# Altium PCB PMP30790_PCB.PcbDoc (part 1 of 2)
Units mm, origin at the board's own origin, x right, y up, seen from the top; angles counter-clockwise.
Board outline 83.5 x 82.5 mm, 4 copper layers (Top Layer, GND, Signal Layer, Bottom Layer), stack 2.155 mm thick; 81 components, 34 nets, 189 pads, 254 vias.
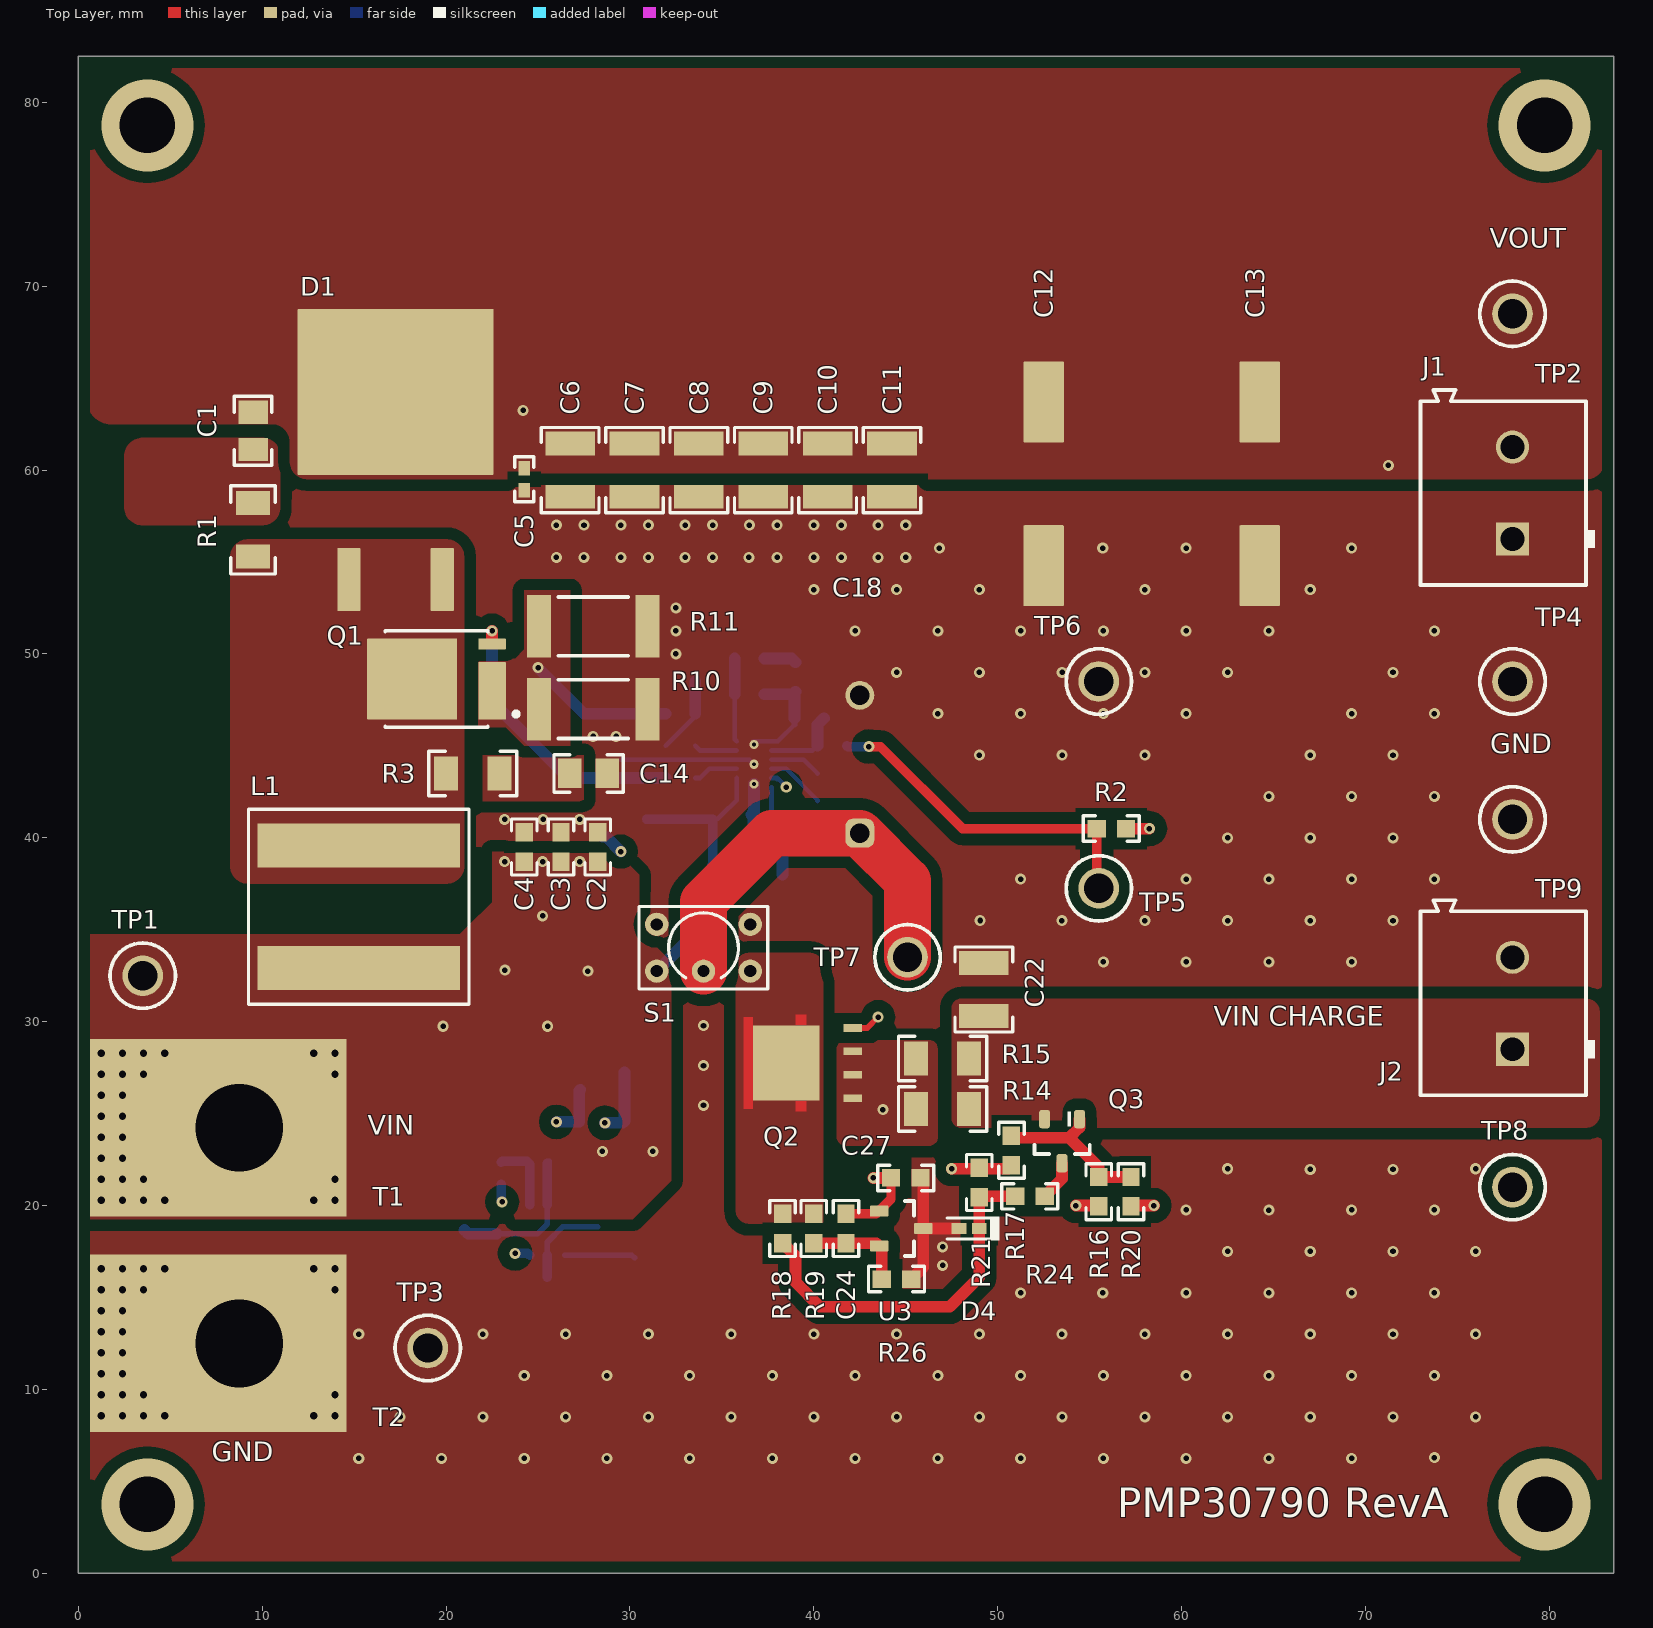
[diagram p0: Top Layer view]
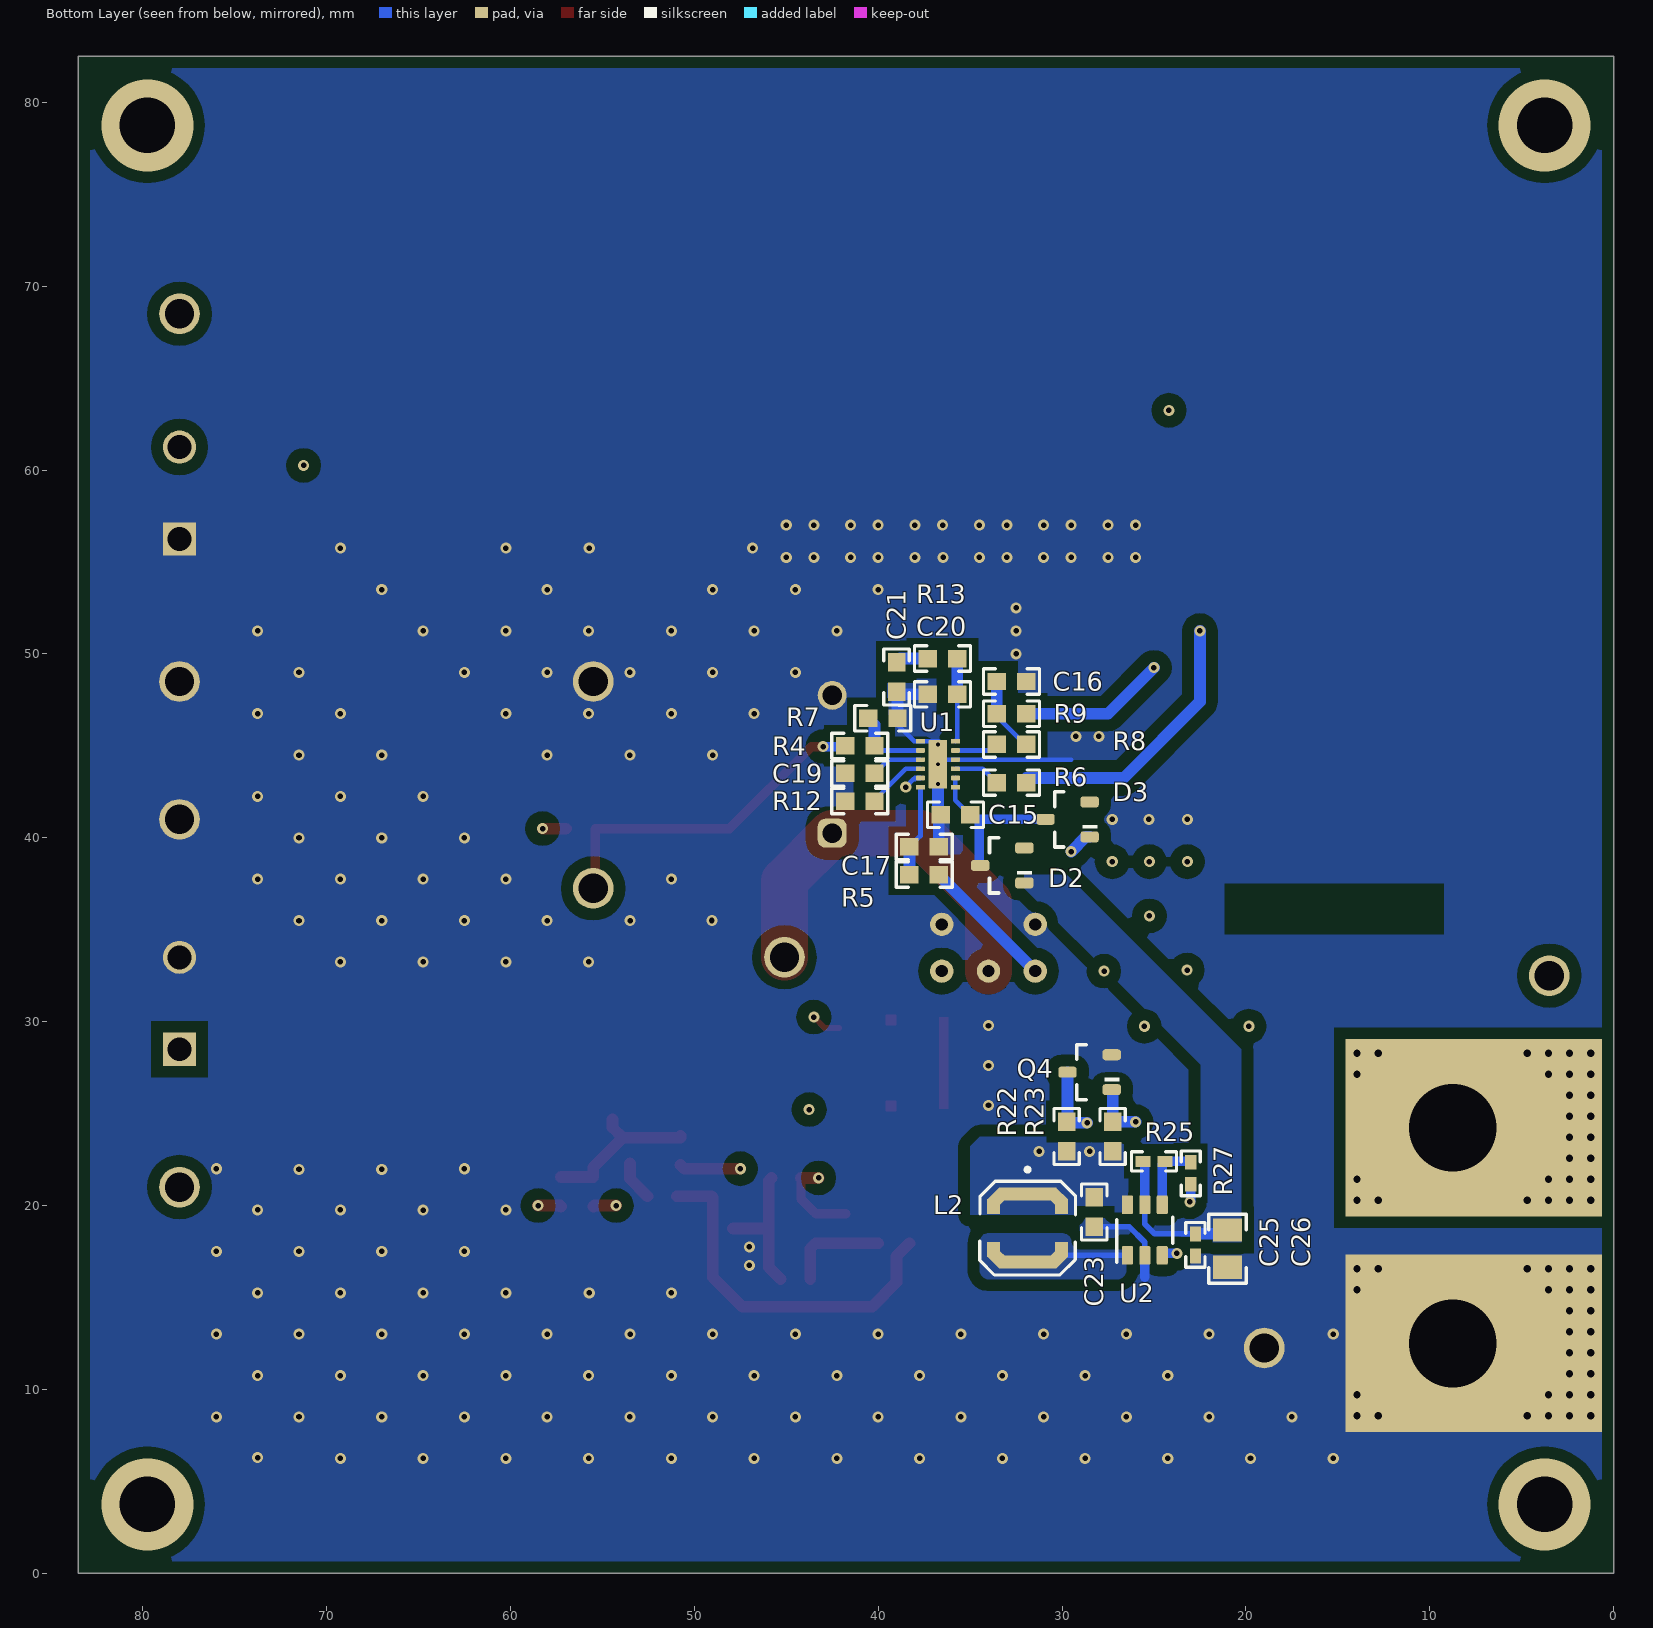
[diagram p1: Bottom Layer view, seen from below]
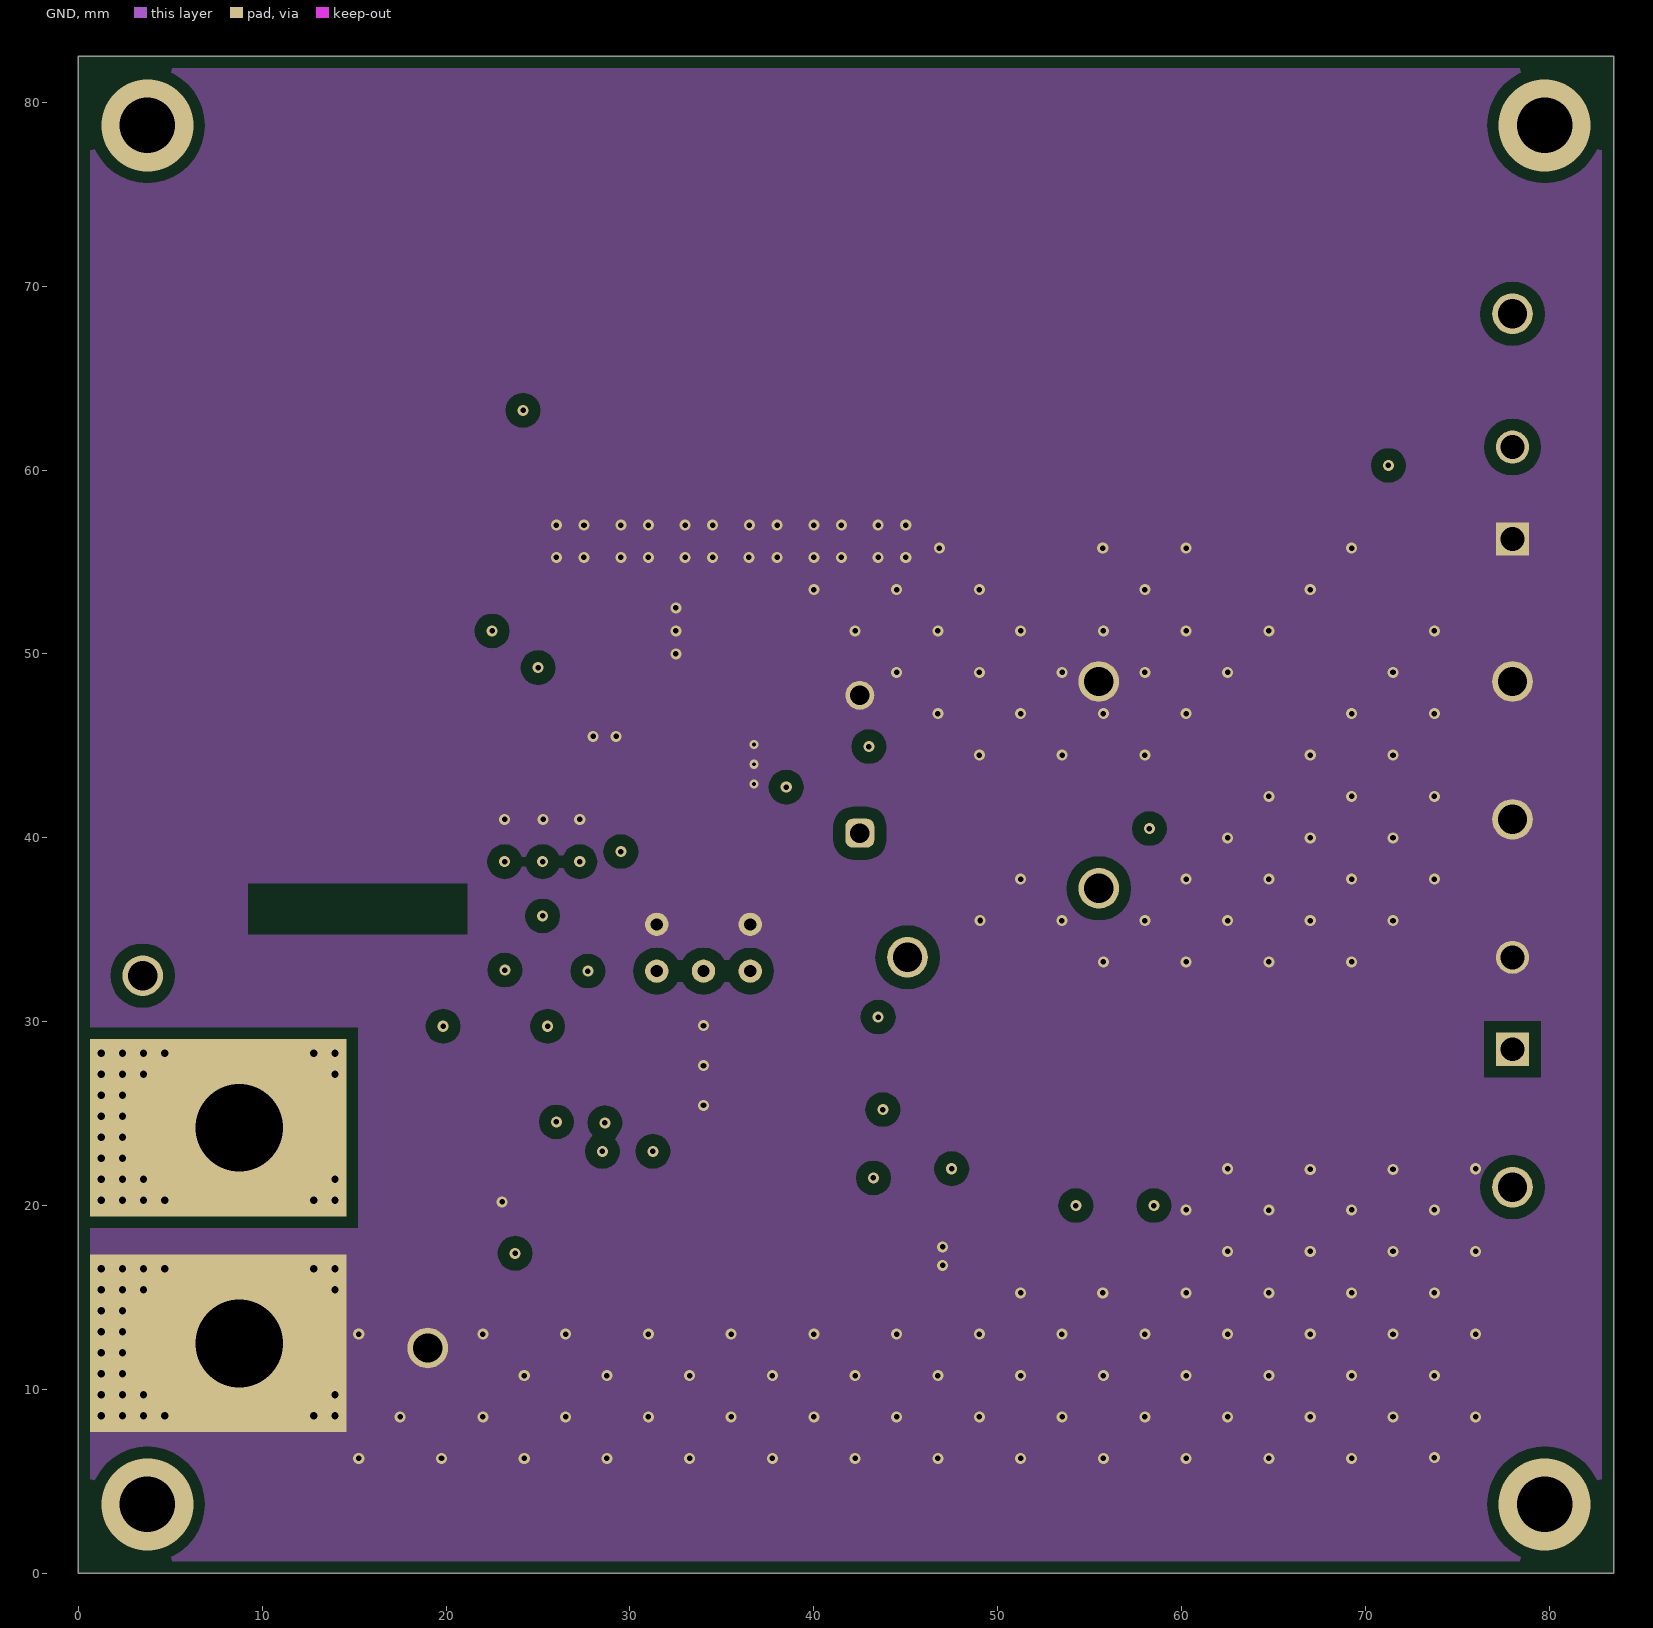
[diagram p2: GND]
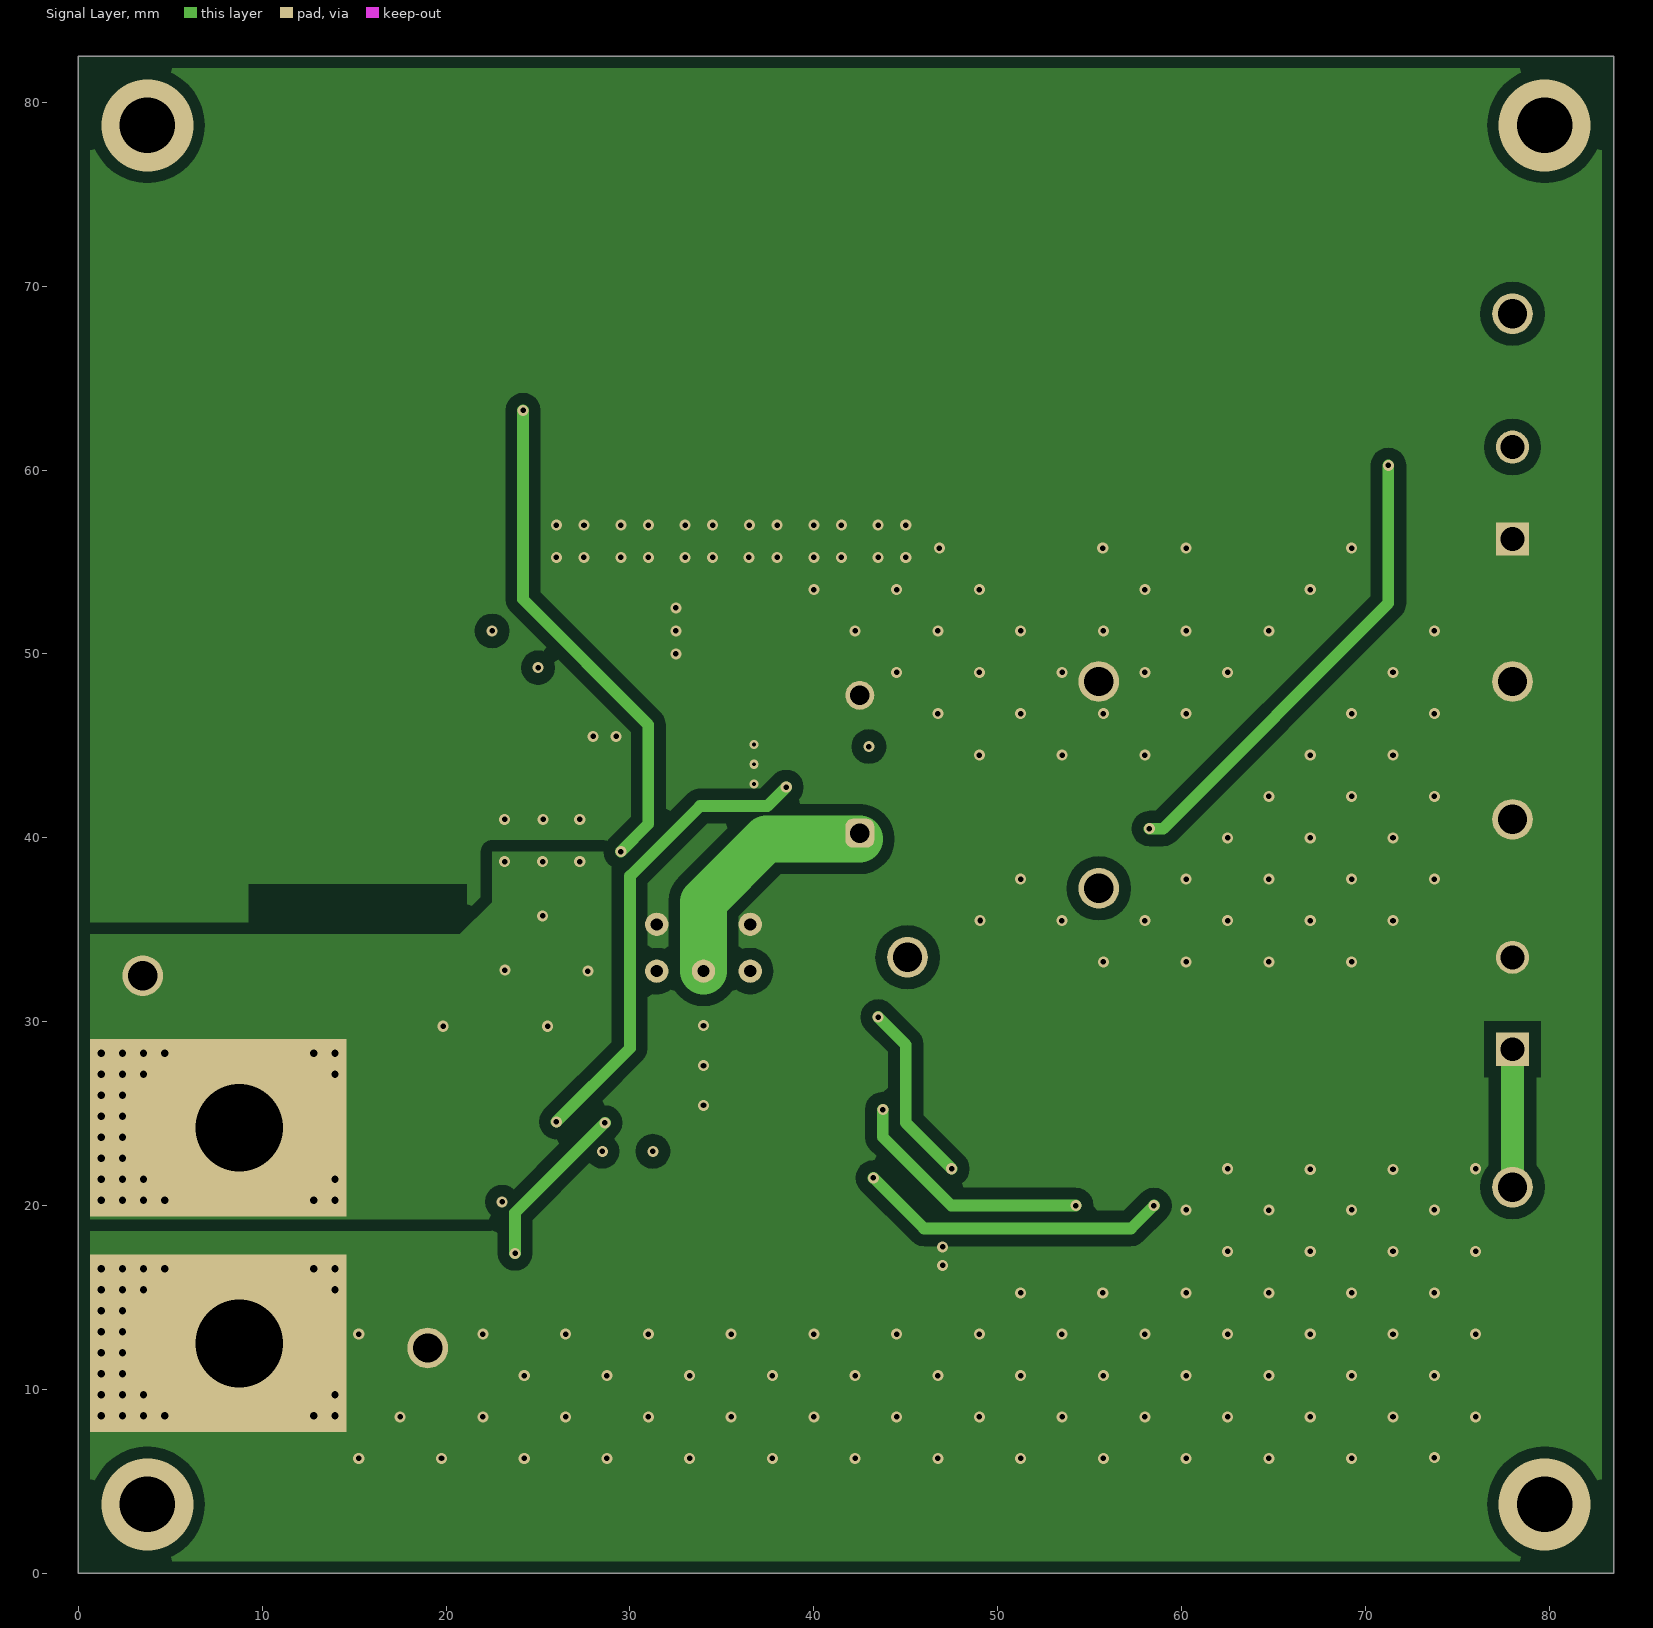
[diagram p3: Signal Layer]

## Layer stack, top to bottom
Top Solder: solder mask 0.0102, Solder Resist, Dk 3.5
Top Layer: signal copper 0.0356
Dielectric 2: dielectric 0.254, Dk 4.2
GND: signal copper 0.036
Dielectric1: core 1.5037, FR-4, Dk 4.8
Signal Layer: signal copper 0.036
Dielectric 3: dielectric 0.254, Dk 4.2
Bottom Layer: signal copper 0.0356
Bottom Solder: solder mask 0.0102, Solder Resist, Dk 3.5

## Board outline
0,0 83.5,0 83.5,82.5 0,82.5

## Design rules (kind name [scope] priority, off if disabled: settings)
AcuteAngle [All] p1: minimum=4.50000000000000E+0001 checktracksonly=FALSE
AssemblyTestPointUsage [All] p1: valid=2
BoardOutlineClearance BoardOutlineClearance_MountingHoles [OnCopper and InComponentClass('Mounting Holes')] p1: gap=1 ignorepadtopadclearanceinfootprint=FALSE
BoardOutlineClearance BoardOutlineClearance_Poly [OnCopper and IsPoly] p2: gap=0.635 ignorepadtopadclearanceinfootprint=FALSE
BoardOutlineClearance [OnCopper and Not InComponentClass('Logo') and not InComponentClass('FiducialMark') and not InRegion(1000,500,4000,800) and not InPoly] p3: gap=1.905 ignorepadtopadclearanceinfootprint=FALSE
Clearance Clearance_Keepouts [((IsTrack Or IsArc) And Not InPoly) And IsFree and IsKeepOut vs ((IsTrack Or IsArc) And Not InPoly) And IsFree and IsKeepOut] p1: gap=0 ignorepadtopadclearanceinfootprint=FALSE
Clearance Clearance_Poly [InPolygon] p2: gap=0.635 ignorepadtopadclearanceinfootprint=TRUE
Clearance Clearance_FiducialMark [IsKeepOut and InComponentClass('FiducialMark') vs IsPad and InComponentClass('FiducialMark')] p3: gap=0 ignorepadtopadclearanceinfootprint=FALSE
Clearance [All] p4: gap=0.2 ignorepadtopadclearanceinfootprint=TRUE
ComponentClearance ComponentClearance_MountingHoles_FiducialMarks [InComponentClass('Mounting Holes') vs InComponentClass('FiducialMark')] p1: gap=1.27 collisioncheckmode=3 verticalgap=0.254 showdistances=FALSE
ComponentClearance ComponentClearance_Shunt [InComponentClass('Header') vs InComponentClass('Shunt')] p2: gap=0 collisioncheckmode=3 verticalgap=0 showdistances=FALSE
ComponentClearance ComponentClearance_Logo [InComponentClass('Logo')] p3: gap=1.27 collisioncheckmode=3 verticalgap=0.254 showdistances=FALSE
ComponentClearance ComponentClearance_ScrewToNut [(HasFootprint('NY PMS 440 0025 PH')) vs (HasFootprint('Keystone_1902C'))] p4: gap=0.127 collisioncheckmode=3 verticalgap=0.254 showdistances=FALSE
ComponentClearance ComponentClearance_MountingHoles [InComponentClass('Mounting Holes')] p5: gap=6.35 collisioncheckmode=3 verticalgap=2540 showdistances=FALSE
ComponentClearance ComponentClearance_SmallPassives [HasFootprint('0201*') or HasFootprint('0402*') or HasFootprint('0508') or HasFootprint('0603*') or HasFootprint('0612') or HasFootprint('0805*') or HasFootprint('0815*') or HasFootprint('0830*') or HasFootprint('1206*') or HasFootprint('1210*') or HasFootprint('1808*') or HasFootprint('1812*') or HasFootprint('1825*') or HasFootprint('2010*') or HasFootprint('2220*') or HasFootprint('2225*') or HasFootprint('2512*') or HasFootprint('2728*') or HasFootprint('3518*') vs HasFootprint('0201*') or HasFootprint('0402*') or HasFootprint('0508') or HasFootprint('0603*') or HasFootprint('0612') or HasFootprint('0805*') or HasFootprint('0815*') or HasFootprint('0830*') or HasFootprint('1206*') or HasFootprint('1210*') or HasFootprint('1808*') or HasFootprint('1812*') or HasFootprint('1825*') or HasFootprint('2010*') or HasFootprint('2220*') or HasFootprint('2225*') or HasFootprint('2512*') or HasFootprint('2728*') or HasFootprint('3518*')] p6: gap=0.38 collisioncheckmode=3 verticalgap=0.254 showdistances=FALSE
ComponentClearance ComponentClearance_THtoSMT [IsThruComponent vs IsSMTComponent] p7: gap=1.016 collisioncheckmode=3 verticalgap=0.762 showdistances=FALSE
ComponentClearance ComponentClearance_THtoTH [IsThruComponent vs IsThruComponent] p8: gap=0.762 collisioncheckmode=3 verticalgap=0.762 showdistances=FALSE
ComponentClearance [All] p9: gap=0.762 collisioncheckmode=3 verticalgap=0.254 showdistances=FALSE
DiffPairsRouting [All] p1: maxlimit=2.54 minlimit=0.254 mostfreqgap=0.254 toplayer_minwidth=0.381 toplayer_maxwidth=0.381 toplayer_prefwidth=0.381 midlayer1_minwidth=0.381 midlayer1_maxwidth=0.381 midlayer1_prefwidth=0.381 midlayer2_minwidth=0.381 midlayer2_maxwidth=0.381 midlayer2_prefwidth=0.381 bottomlayer_minwidth=0.381 bottomlayer_maxwidth=0.381 bottomlayer_prefwidth=0.381 maxuncoupledlength=25.4
FabricationTestPointUsage TestPointUsage [All] p1: valid=2 allowmultiple=FALSE
FabricationTestpoint Testpoint [All] p1: side=3 testpointundercomponent=TRUE minsize=1.016 maxsize=2.54 preferedsize=1.524 minholesize=0 maxholesize=1.016 preferedholesize=0.813 testpointgrid=0.025 allowsidetop=TRUE allowsidebottom=TRUE usegrid=TRUE gridtolerance=0
FanoutControl Fanout_LCC [IsLCC] p1: bgadir=Out bgaviamode=Centered fanoutstyle=Auto fanoutdirection=Alternating viagrid=0.025 // Fanout_LCC (Default Rule)
FanoutControl Fanout_BGA [IsBGA] p2: bgadir=Out bgaviamode=Centered fanoutstyle=Auto fanoutdirection=Alternating viagrid=0.025 // Fanout_BGA (Default Rule)
FanoutControl Fanout_Default [All] p4: bgadir=Out bgaviamode=Centered fanoutstyle=Auto fanoutdirection=Alternating viagrid=0.025 // Fanout_Default (Default Rule)
FanoutControl Fanout_Small [(CompPinCount < 5)] p5: bgadir=Out bgaviamode=Centered fanoutstyle=Auto fanoutdirection=OutThenIn viagrid=0.025 // Fanout_Small (Default Rule)
HoleSize [All] p1: absolutevalues=TRUE maxlimit=6.375 minlimit=0.2 maxpercent=80.000 minpercent=20.000
MinimumAnnularRing MinimumAnnularRing_ThermalPadVias [IsVia and InAnyComponent] p1: minimumring=0.15
MinimumAnnularRing [All] p2: minimumring=0.2
MinimumSolderMaskSliver MinimumSolderMaskSliver_Logo [InComponentClass('Logo') vs InComponentClass('Logo')] p1: minsoldermaskwidth=0.018
MinimumSolderMaskSliver [All] p2: minsoldermaskwidth=0.1
PlaneConnect [All] p1: planeconnectstyle=Direct reliefexpansion=0.254 reliefentries=4 reliefconductorwidth=0.254 reliefairgap=0.254
PolygonConnect PolygonConnect_1 [All vs IsNamedPolygon('TOP_LAYER_NETD1_1_P000')] p1: connectstyle=Direct reliefconductorwidth=0.254 reliefentries=4 polygonreliefangle="90 Angle" airgapwidth=0.254
PolygonConnect [All] p2: connectstyle=Direct reliefconductorwidth=0.254 reliefentries=4 polygonreliefangle="90 Angle" airgapwidth=0.254
RoutingVias ThermalPadVias [IsVia and InAnyComponent] p1: holewidth=0.2 width=0.5 viastyle="Through Hole" minholewidth=0.2 minwidth=0.5 maxholewidth=0.33 maxwidth=0.6
RoutingVias [All] p2: holewidth=0.406 width=0.864 viastyle="Through Hole" minholewidth=0.2 minwidth=0.66 maxholewidth=1.016 maxwidth=1.651
SilkToBoardRegionClearance [Not ((IsComment or IsDesignator) And (Hide <> 'False')) and not InRegion(1000,500,4000,800)] p1:
SilkToSilkClearance SilkToSilkClearance_Pb-FreeLogo [(HasFootprint('Pb-Free_Overlay_Medium') OR HasFootprint('Pb-Free_Overlay_Small')) vs (HasFootprint('Pb-Free_Overlay_Medium') OR HasFootprint('Pb-Free_Overlay_Small'))] p1: silktosilkclearance=0
SilkToSilkClearance [All] p2: silktosilkclearance=0.1
SilkToSolderMaskClearance SilkToComponentPadClearance [(IsPad or IsFill or IsRegion) and InAnycomponent] p1: minsilkscreentomaskgap=0.127 clearancetoexposedcopper=TRUE
SilkToSolderMaskClearance "Silk to Solder Mask Opening" [All] p2: minsilkscreentomaskgap=0.1 clearancetoexposedcopper=FALSE
SolderMaskExpansion [All] p1: expansion=0.05
UnRoutedNet [All] p1: checkbadconnections=TRUE
Width [All] p1: maxlimit=2.54 minlimit=0.152 preferedwidth=0.254 checkconnectedcopper=TRUE
14 further rules are at their usual default settings.

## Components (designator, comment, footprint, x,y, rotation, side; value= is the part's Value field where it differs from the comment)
C1 "GRM21AR72E102KW01D" 0805_HV 9.5,62.134 r270 top value=1000pF
C2 "GRM188Z71A106MA73D" 0603 28.25,39.5 r90 top value=10uF
C3 "GRM188Z71A106MA73D" 0603 26.25,39.5 r90 top value=10uF
C4 "GRM188Z71A106MA73D" 0603 24.25,39.5 r90 top value=10uF
C5 "GRM155R71C104JA88D" 0402 24.25,59.5 r270 top value=0.1uF
C6 "GRM32ER71E226KE15L" 1210_270 26.75,60 r270 top value=22uF
C7 "GRM32ER71E226KE15L" 1210_270 30.25,60 r270 top value=22uF
C8 "GRM32ER71E226KE15L" 1210_270 33.75,60 r270 top value=22uF
C9 "GRM32ER71E226KE15L" 1210_270 37.25,60 r270 top value=22uF
C10 "GRM32ER71E226KE15L" 1210_270 40.75,60 r270 top value=22uF
C11 "GRM32ER71E226KE15L" 1210_270 44.25,60 r270 top value=22uF
C12 "HHXB160ARA471MJA0G" FP-HHXB160ARA471MJA0G_RADIAL-MFG 52.5,59.25 r90 top
C13 "HHXB160ARA471MJA0G" FP-HHXB160ARA471MJA0G_RADIAL-MFG 64.25,59.25 r90 top
C14 "GRM21AR72E102KW01D" 0805_HV 27.75,43.5 r0 top value=1000pF
C15 "GRM188Z71C225KE43" 0603 35.8,41.25 r0 bottom value=2.2uF
C16 "GRM188R71C102KA01D" 0603 32.75,48.5 r180 bottom value=1000pF
C17 "GRM188R71C104KA01D" 0603 37.5,39.5 r180 bottom value=0.1uF
C18 "JUMT1226MHD" JUM_1600x3150 42.5,44 r90 top value=22000000uF
C19 "GRM188R71C104KA01D" 0603 41,43.5 r0 bottom value=0.1uF
C20 "GRM188R71H223KA01D" 0603 36.5,47.8 r0 bottom value=0.022uF
C21 "GRM188R71A684KA61D" 0603 39,48.75 r270 bottom value=0.68uF
C22 "GRM32ER71H475KA88L" 1210_270 49.25,31.75 r90 top value=4.7uF
C23 "GRM188Z71A106MA73D" 0603 28.25,19.65 r270 bottom value=10uF
C24 "GRM188R72A102KA01D" 0603 41.75,18.75 r270 top value=1000pF
C25 "GRM155R71A104KA01D" 0402 22.75,17.856 r270 bottom value=0.1uF
C26 "GRM21BZ71E106KE15L" 0805_HV 21,17.65 r270 bottom value=10uF
C27 "GRM188R72A102KA01D" 0603 45,21.5 r0 top value=1000pF
D1 "MBRB1535CTPBF" DDPAK 17.25,60.3 r90 top value=35V
D2 "BAS16LT1G" SOT-23 33.25,38.5 r0 bottom value=100V
D3 "BAS16LT1G" SOT-23 29.7,41 r0 bottom value=100V
D4 "DNP" SOD-523 48.45,18.75 r180 top value=2.7V
J1 "691 101 710 002" Wurth_691101710002 78,58.75 r90 top
J2 "691 101 710 002" Wurth_691101710002 78,31 r90 top
L1 "XAL1060-122MEB" XAL1060 15.25,36.25 r90 top value=1.2uH
L2 "LPS4018-103MRB" LPS4018 31.876,18.774 r270 bottom value=10uH
Q1 "IAUC120N04S6N010ATMA1" FP-IAUC120N04S6N009ATMA1_TDSON8-MFG 19.48,48.635 r90 top
Q2 "SQJ415EP-T1_GE3" PowerPAK_SO-8L 39.305,27.75 r180 top value=-60V
Q3 "MMBT2907ALT1G" SOT-23 53.5,23.5 r270 top value="60 V"
Q4 "RUC002N05HZGT116" SOT-23_Rohm 28.5,27.25 r0 bottom value=50V
R1 "CRCW12061R00JNEA" 1206 9.5,56.75 r90 top value=1.0
R2 "CRCW060349R9FKEA" 0603 56.179,40.5 r0 top value=49.9
R3 "CRCW12061R00JNEA" 1206 21.45,43.5 r0 top value=1.0
R4 "CRCW060380K6FKEA" 0603 41,45 r0 bottom value=80.6k
R5 "CRCW060310K0FKEA" 0603 37.5,38 r180 bottom value=10.0k
R6 "CRCW06030000Z0EA" 0603 32.75,43 r180 bottom value=0
R7 "CRCW060310K0FKEA" 0603 39.75,46.5 r0 bottom value=10.0k
R8 "CRCW06031K00FKEA" 0603 32.75,45.075 r180 bottom value=1.00k
R9 "CRCW0603100RFKEA" 0603 32.75,46.75 r180 bottom value=100
R10 "CSNL2512FT5L00" 2512 28,47 r180 top value=0.005
R11 "CSNL2512FT4L00" 2512 28,51.5 r180 top value=0.004
R12 "CRCW0603110KFKEA" 0603 41,42 r180 bottom value=110k
R13 "CRCW06031K00FKEA" 0603 36.5,49.75 r180 bottom value=1.00k
R14 "CRCW120610R0FKEA" 1206 47,25.25 r180 top value=10.0
R15 "CRCW120610R0FKEA" 1206 47,28 r180 top value=10.0
R16 "CRCW0603200RFKEA" 0603 55.5,20.75 r270 top value=200
R17 "CRCW06030000Z0EA" 0603 50.75,23 r270 top value=0
R18 "CRCW060310K0FKEA" 0603 38.3,18.75 r90 top value=10.0k
R19 "CRCW0603200RFKEA" 0603 40,18.75 r90 top value=200
R20 "CRCW06032K00FKEA" 0603 57.25,20.75 r90 top value=2.00k
R21 "CRCW0603100RFKEA" 0603 49,21.25 r90 top value=100
R22 "CRCW0603100KJNEA" 0603 29.75,23.75 r270 bottom value=100k
R23 "CRCW0603100KJNEA" 0603 27.25,23.75 r270 bottom value=100k
R24 "CRCW06030000Z0EA" 0603 51.75,20.5 r180 top value=0
R25 "CRCW040290K9FKED" 0402 25,22.4 r0 bottom value=90.9k
R26 "CRCW060310K0FKEA" 0603 44.5,16 r180 top value=10.0k
R27 "CRCW040210K0FKED" 0402 23,21.75 r90 bottom value=10.0k
S1 "G13AP" SW_G1xAP 34,34.02 r0 top
T1 "CB35-36-CY" CB35-36-CY 8.75,24.225 r0 top
T2 "CB35-36-CY" CB35-36-CY 8.75,12.5 r0 top
TP1 "5010" Keystone5010 3.5,32.5 r0 top
TP2 "5010" Keystone5010 78,68.5 r0 top
TP3 "5011" Keystone5011 19,12.25 r0 top
TP4 "5011" Keystone5011 78,48.5 r0 top
TP5 "5014" Keystone5014 55.5,37.25 r0 top
TP6 "5011" Keystone5011 55.5,48.5 r0 top
TP7 "5010" Keystone5010 45.097,33.5 r0 top
TP8 "5010" Keystone5010 78,21 r0 top
TP9 "5011" Keystone5011 78,41 r0 top
U1 "LM5155QDSSRQ1" DSS0012C 36.75,44 r0 bottom
U2 "TPS61071TDDCRQ1" DDC0006A_N 25.5,18.666 r90 bottom
U3 "TL431AQDBZRQ1" DBZ0003A_N 44.75,18.75 r0 top

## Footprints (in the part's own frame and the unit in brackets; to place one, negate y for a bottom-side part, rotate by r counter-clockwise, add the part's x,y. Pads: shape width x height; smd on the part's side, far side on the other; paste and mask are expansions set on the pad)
0402 [mm] "0402 from SM-752 data"
  rect 0.8x0.6 smd: 1(-0.6,0) 2(0.6,0)
  silkscreen extent -1.22,-0.52 1.22,0.52, body extent -0.55,-0.3 0.55,0.3, height 0.6
0603 [mm] "0603 from SM-752 data"
  rect 1x0.95 smd: 1(-0.8,0) 2(0.8,0)
  silkscreen extent -1.52,-0.69 1.52,0.69, body extent -0.87,-0.47 0.87,0.47, height 1
0805_HV [mil] "0805 with 30mil clearance between pads"
  rect 50x63 smd: 1(-40,0) 2(40,0)
  silkscreen extent -74,-40 74,40, body extent -43,-29 43,29, height 57
1206 [mm] "1206 from SM-752 data"
  rect 1.3x1.85 smd: 1(-1.45,0) 2(1.45,0)
  silkscreen extent -2.4,-1.21 2.4,1.21, body extent -1.7,-0.9 1.7,0.9, height 1.35
1210_270 [mm] "1210"
  rect 1.3x2.7 smd: 1(-1.45,0) 2(1.45,0)
  silkscreen extent -2.32,-1.57 2.32,1.57, body extent -1.7,-1.35 1.7,1.35, height 2.7
2512 [mm] "Chip Resistor, Body 6.3x3.2mm, IPC Medium Density"
  rect 1.3x3.4 smd: 1(-2.95,0) 2(2.95,0)
  silkscreen extent -1.9,-1.6 1.9,1.6, body extent -3.22,-1.67 3.22,1.67, height 0.71
CB35-36-CY [mil] "Terminal 50A Lug"
  rect 550x380 hole 188 copper offset -45,0 paste-190: 1(0,0)
  body extent -960,-189 230,191, height 614
DBZ0003A_N [mm] "SOT23, 3-Leads, Body 2.9x1.3mm, Pitch 0.95mm, Lead Span 2.4mm, IPC Medium Density"
  rrect17% 1x0.6 smd: 1(-1.2,0.95) 2(-1.2,-0.95) 3(1.2,0)
  silkscreen extent 0.2,-1.5 0.7,1.5, body extent -1.26,-1.46 1.26,1.46, height 0.98
DDC0006A_N [mm]
  rrect17% 1x0.6 smd: 1(-1.375,0.95) 2(-1.375,0) 3(-1.375,-0.95) 4(1.375,-0.95) 5(1.375,0) 6(1.375,0.95)
  silkscreen extent -1.75,-1.52 0.7,1.53, body extent -1.43,-1.48 1.43,1.49, height 0.92
DDPAK [mil] "D2-PAK, 3-Pads, Body 9.7x10.4mm (max), TO-263AB, using Vishay Silionix recommended pad sizes"
  rrect8% 135x49.49 smd: 1(-246.06,100) 3(-246.06,-100)
  rrect1% 355x420 smd paste-181.1: 2(155.51,0)
  body extent -295,-202 324,202, height 180
DSS0012C [mm] "WSON-12"
  rrect40% 0.5x0.25 smd: 1(-0.95,1.25) 2(-0.95,0.75) 3(-0.95,0.25) 4(-0.95,-0.25) 5(-0.95,-0.75) 6(-0.95,-1.25) 7(0.95,-1.25) 8(0.95,-0.75) 9(0.95,-0.25) 10(0.95,0.25) 11(0.95,0.75) 12(0.95,1.25)
  rrect11% 0.95x1.17 on Bottom Paste: 13(0,-0.685) 13(0,0.685)
  rrect11% 1x2.65 smd paste-0.5: 13(0,0)
  body extent -1,-1.5 1,1.5, height 0.81
FP-HHXB160ARA471MJA0G_RADIAL-MFG [mm]
  rrect5% 4.4x2.2 smd paste+0 mask+0: 1(-4.45,0) 2(4.45,0)
  body extent -6.9,-5.5 6.9,5.5, height 0.25
FP-IAUC120N04S6N009ATMA1_TDSON8-MFG [mm]
  rrect7% 3.14x1.5 smd paste-1000 mask-1000: 1-2-3(-0.635,-3.02)
  rrect17% 0.6x1.5 smd paste-1000 mask+0: 4(1.905,-3.02)
  rrect2% 4.41x4.9 smd paste-1000 mask-1000: 5-6-7-8(0,1.325)
  silkscreen extent -2.63,-4.45 2.63,2.79, body extent -2.96,-3.87 2.96,3.88, height 0.25
JUM_1600x3150 [mm] "TH, 2-Leads, Dia 16mm, Lead Spacing 7.5mm"
  rrect50% 1.575x1.575 hole 1.05: 1(-3.75,0)
  round 1.575 hole 1.05: 2(3.75,0)
  body extent -8.25,-8.25 8.25,8.25, height 33.5
Keystone5010 [mil] "Keystone Multipurpose loops"
  round 87 hole 63: 1(0,0)
  silkscreen extent -70,-70 70,70, body extent -63,-63 63,62, height 319
Keystone5011 [mil] "Keystone Multipurpose loops"
  round 87 hole 63: 1(0,0)
  silkscreen extent -70,-70 70,70, body extent -63,-63 63,62, height 319
Keystone5014 [mil] "Keystone Multipurpose loops"
  round 87 hole 63: 1(0,0)
  silkscreen extent -70,-70 70,70, body extent -63,-63 63,62, height 319
LPS4018 [mil]
  rect 28x123 smd: 1(-72.5,0) 2(72.5,0)
  rect 35.5x28 smd rot 135: 1(-64,-64) 2(64,64)
  rect 35.5x28 smd rot 45: 1(-64,64) 2(64.5,-63.5)
  rect 31.5x28 smd: 1(-46,-72.5) 1(-46,72.5) 2(46,-72.5) 2(46,72.5)
  silkscreen extent -129,-103 101,103, body extent -81,-81 81,81, height 71
PowerPAK_SO-8L [mm] "based on Vishay recommended land pattern Document 63818 Feb 7, 2012"
  rect 1x0.41 smd: 1(-2.805,1.905) 2(-2.805,0.635) 3(-2.805,-0.635) 4(-2.805,-1.905)
  rect 3.63x4.061 smd: 5(0.805,0)
  Top Layer region: 2.615,-2.5 3.125,-2.5 3.125,2.5 2.615,2.5
  Top Layer region: -0.298,2.03 0.297,2.03 0.297,2.64 -0.298,2.64
  Top Layer region: -0.298,-2.64 0.298,-2.64 0.298,-2.03 -0.298,-2.03
  body extent -3.07,-2.57 3.08,2.57, height 1.21
SOD-523 [mm] "NXP Semiconductor recommended land pattern, nominal STEP model"
  rect 0.8x0.6 smd paste-0.05: 1(-0.55,0) 2(0.55,0)
  silkscreen extent -1.65,-0.66 1.2,0.66, body extent -0.8,-0.4 0.8,0.4, height 0.72
SOT-23 [mm] "SOT23, 3-Leads, Body 2.9x1.3mm, Pitch 0.95mm, Lead Span 2.5mm, IPC Medium Density"
  rrect50% 1x0.6 smd: 1(-1.2,0.95) 2(-1.2,-0.95) 3(1.2,0)
  silkscreen extent -1.63,-1.5 0.7,1.5, body extent -1.16,-1.45 1.21,1.45, height 1
SOT-23_Rohm [mm] "SOT23, 3-Leads, Body 2.9x1.3mm, Pitch 0.95mm, Lead Span 2.5mm"
  rrect50% 1x0.6 smd: 1(-1.2,0.95) 2(-1.2,-0.95) 3(1.2,0)
  silkscreen extent -1.63,-1.5 0.7,1.5, body extent -1.16,-1.45 1.21,1.45, height 1
SW_G1xAP [mil] "Switch, NKK G Series"
  round 50 hole 26: 1(-100,50) 3(100,50) 4(-100,-50) 5(0,-50) 6(100,-50)
  silkscreen extent -138,-88 138,89, body extent -138,-88 138,89, height 424
Wurth_691101710002 [mm] "Terminal Block, 5 mm, 2x1, TH"
  rect 1.8x1.8 hole 1.3: 1(-2.5,0)
  round 1.8 hole 1.3: 2(2.5,0)
  silkscreen extent -5,-4.5 5.6,5, body extent -5.6,-4 5.6,5, height 12.5
XAL1060 [mm] "COILCRAFT"
  rect 2.39x11 smd: 1(-3.325,0) 2(3.325,0)
  silkscreen extent -5.3,-6 5.3,6, body extent -5.25,-5.9 5.25,5.9, height 6

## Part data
C1 C14: library part CMP-0008251-2, "CAP, CERM, 1000 pF, 250 V, +/- 10%, X7R, 0805", Cap_Case=0805, Manufacturer=MuRata, Supplier Part Number 1=490-3525-1-ND, TempCo=X7R, Tolerance_%=10%, Value1=Unknown, Value2=250V, ValueDisplayed=1000pF
C2 C3 C4 C23: library part CMP-0007497-5, "CAP, CERM, 10 uF, 10 V, +/- 20%, X7R, 0603", Cap_Case=0603, Manufacturer=MuRata, Supplier Part Number 1=81-GRM188Z71A106MA3D, TempCo=X7R, Tolerance_%=20%, Value1=Unknown, Value2=10V, ValueDisplayed=10uF
C5: library part CMP-0006640-2, "CAP, CERM, 0.1 uF, 16 V, +/- 5%, X7R, 0402", Cap_Case=0402, Manufacturer=MuRata, Supplier Part Number 1=490-6327-1-ND, TempCo=X7R, Tolerance_%=5%, Value1=Unknown, Value2=16V, ValueDisplayed=0.1uF
C6 C7 C8 C9 C10 C11: library part CMP-0009224-2, "CAP, CERM, 22 uF, 25 V, +/- 10%, X7R, 1210", Cap_Case=1210, Manufacturer=MuRata, Supplier Part Number 1=490-5313-1-ND, TempCo=X7R, Tolerance_%=10%, Value1=Unknown, Value2=25V, ValueDisplayed=22uF
C12 C13: library part CMP-0086437-1, "Cap Aluminum Polymer 470uF 16VDC 20% (10 X 10mm) SMD 0.018 Ohm 2600mA 5000h 105C Automotive T/R", Manufacturer="United Chemi-Con", Tolerance_%=20%
C15: library part CMP-0007499-4, "CAP, CERM, 2.2 uF, 16 V, +/- 10%, X7R, 0603", Cap_Case=0603, Manufacturer=MuRata, Supplier Part Number 1=81-GRM188Z71C225KE3D, TempCo=X7R, Tolerance_%=10%, Value1=Unknown, Value2=16V, ValueDisplayed=2.2uF
C16: library part CMP-0007376-4, "CAP, CERM, 1000 pF, 16 V, +/- 10%, X7R, 0603", Cap_Case=0603, Manufacturer=MuRata, Supplier Part Number 1=GRM188R71C102KA01D-ND, TempCo=X7R, Tolerance_%=10%, Value1=Unknown, Value2=16V, ValueDisplayed=1000pF
C17 C19: library part CMP-0007378-5, "CAP, CERM, 0.1 uF, 16 V, +/- 10%, X7R, 0603", Cap_Case=0603, Manufacturer=MuRata, Supplier Part Number 1=490-1532-1-ND, TempCo=X7R, Tolerance_%=10%, Value1=Unknown, Value2=16V, ValueDisplayed=0.1uF
C18: library part CMP-0084050-1, "CAP, Electric Double Layer, 22000000 µF, 2.7 V,+/- 20%, 0.07 ohm, TH", Cap_Case=16x31.5mm, Manufacturer=Nichicon, Tolerance_%=20%, Value1="0.07 ohm", Value2=2.7V, ValueDisplayed=22F
C20: library part CMP-0007444-4, "CAP, CERM, 0.022 uF, 50 V, +/- 10%, X7R, 0603", Cap_Case=0603, Manufacturer=MuRata, Supplier Part Number 1=490-1517-1-ND, TempCo=X7R, Tolerance_%=10%, Value1=Unknown, Value2=50V, ValueDisplayed=0.022uF
C21: library part CMP-0007375-4, "CAP, CERM, 0.68 uF, 10 V, +/- 10%, X7R, 0603", Cap_Case=0603, Manufacturer=MuRata, Supplier Part Number 1=GRM188R71A684KA61D-ND, TempCo=X7R, Tolerance_%=10%, Value1=Unknown, Value2=10V, ValueDisplayed=0.68uF
C22: library part CMP-0009228-2, "CAP, CERM, 4.7 uF, 50 V, +/- 10%, X7R, 1210", Cap_Case=1210, Manufacturer=MuRata, Supplier Part Number 1=490-1864-1-ND, TempCo=X7R, Tolerance_%=10%, Value1="0.002 ohm", Value2=50V, ValueDisplayed=4.7uF
C24 C27: library part CMP-0007467-4, "CAP, CERM, 1000 pF, 100 V, +/- 10%, X7R, 0603", Cap_Case=0603, Manufacturer=MuRata, Supplier Part Number 1=490-1472-1-ND, TempCo=X7R, Tolerance_%=10%, Value1=Unknown, Value2=100V, ValueDisplayed=1000pF
C25: library part CMP-0006629-2, "CAP, CERM, 0.1 uF, 10 V, +/- 10%, X7R, 0402", Cap_Case=0402, Manufacturer=MuRata, Supplier Part Number 1=GRM155R71A104KA01D-ND, TempCo=X7R, Tolerance_%=10%, Value1=Unknown, Value2=10V, ValueDisplayed=0.1uF
C26: library part CMP-0008378-2, "CAP, CERM, 10 uF, 25 V, +/- 10%, X7R, 0805", Cap_Case=0805, Manufacturer=MuRata, Supplier Part Number 1=81-GRM21BZ71E106KE5L, TempCo=X7R, Tolerance_%=10%, Value1=Unknown, Value2=25V, ValueDisplayed=10uF
D1: library part CMP-0028556-3, "Diode, Schottky, 35 V, 15 A, DDPAK", Manufacturer="International Rectifier", Value1=15A, Value2=0.8V
D2 D3: library part CMP-0029193-2, "Diode, Switching, 100 V, 0.2 A, SOT-23", Manufacturer="ON Semiconductor", Value1=0.2A, Value2=1.25V
D4: library part CMP-0005892-4, "Diode, Zener, 2.7 V, 300 mW, SOD-523", Manufacturer="Diodes Inc.", PartNumber=BZT52C2V7T-7, Power_W=300mW, Value1=0.3W
J1 J2: library part CMP-0054828-1, "Terminal Block, 5 mm, 2x1, Tin, TH", Manufacturer="Wurth Elektronik", Supplier Part Number 1=732-2026-ND
L1: library part CMP-0060959-1, "Inductor, Shielded, Composite, 1.2 uH, 26.3 A, 0.0025 ohm, AEC-Q200 Grade 1, SMD", Manufacturer=Coilcraft, Supplier Part Number 1=994-XAL1060-122MEB, Value1="0.0025 ohm", Value2=26.3A, ValueDisplayed=1.2uH
L2: library part CMP-0060471-1, "Inductor, Shielded Drum Core, Ferrite, 10 uH, 1.25 A, 0.18 ohm, SMD", Manufacturer=Coilcraft, Supplier Part Number 1=994-LPS4018-103MRB, Value1="0.18 ohm", Value2=1.25A, ValueDisplayed=10uH
Q1: library part CMP-0086959-1, "Trans Mosfet N-ch 40V 120A 8-PIN Pg-tdson T/R", Manufacturer=Infineon
Q2: library part CMP-0083987-2, "MOSFET, P-CH, -40 V, -30 A, AEC-Q101, PowerPAK_SO-8L", Alternate Manufacturer=None, Manufacturer=Vishay-Semiconductor, Value1="0.024 ohm", Value2="73 nC"
Q3: library part CMP-0000344-2, "Transistor, PNP, 60 V, 0.6 A, SOT-23", Manufacturer="ON Semiconductor", Supplier Part Number 1=MMBT2907ALT1GOSCT-ND, Value1="0.6 A"
Q4: library part CMP-0085604-2, "MOSFET, N-CH, 50 V, 0.2 A, AEC-Q101, SOT-23", Alternate Manufacturer=None, Manufacturer=Rohm, Value1="2.2 ohm", Value2="? nC"
R1 R3: library part CMP-0018617-3, "RES, 1.0, 5%, 0.25 W, AEC-Q200 Grade 0, 1206", Manufacturer=Vishay-Dale, Power_W=250mW, Supplier Part Number 1=541-1.0ECT-ND, TempCo="200 ppm/C", Tolerance_%=5%, Value2=0.25W, Value_Code=1R00, ValueDisplayed=DNP
R2: library part CMP-0022448-4, "RES, 49.9, 1%, 0.1 W, AEC-Q200 Grade 0, 0603", Manufacturer=Vishay-Dale, Power_W=100mW, Supplier Part Number 1=541-49.9HCT-ND, TempCo="100 ppm/C", Tolerance_%=1%, Value2=0.1W, Value_Code=49R9, ValueDisplayed=49.9
R4: library part CMP-0022616-4, "RES, 80.6 k, 1%, 0.1 W, AEC-Q200 Grade 0, 0603", Manufacturer=Vishay-Dale, Power_W=100mW, Supplier Part Number 1=541-80.6KHCT-ND, TempCo="100 ppm/C", Tolerance_%=1%, Value2=0.1W, Value_Code=80k6, ValueDisplayed=80.6k
R5 R7 R18 R26: library part CMP-0021998-4, "RES, 10.0 k, 1%, 0.1 W, AEC-Q200 Grade 0, 0603", Manufacturer=Vishay-Dale, Power_W=100mW, Supplier Part Number 1=541-10.0KHCT-ND, TempCo="100 ppm/C", Tolerance_%=1%, Value2=0.1W, Value_Code=10k0, ValueDisplayed=10.0k
R6 R24: library part CMP-0025697-1, "RES, 0, 5%, 0.1 W, 0603", Manufacturer=Vishay-Dale, Power_W=100mW, Supplier Part Number 1=541-0.0GCT-ND, TempCo="200 ppm/C", Tolerance_%=5%, Value2=0.1W, Value_Code=0000, ValueDisplayed=0
R8 R13: library part CMP-0022109-5, "RES, 1.00 k, 1%, 0.1 W, AEC-Q200 Grade 0, 0603", Manufacturer=Vishay-Dale, Power_W=100mW, Supplier Part Number 1=541-1.00KHCT-ND, TempCo="100 ppm/C", Tolerance_%=1%, Value2=0.1W, Value_Code=1k00, ValueDisplayed=1.00k
R9 R21: library part CMP-0021991-4, "RES, 100, 1%, 0.1 W, AEC-Q200 Grade 0, 0603", Manufacturer=Vishay-Dale, Power_W=100mW, Supplier Part Number 1=541-100HCT-ND, TempCo="100 ppm/C", Tolerance_%=1%, Value2=0.1W, Value_Code=100R, ValueDisplayed=100
R10: library part CMP-0015758-2, "RES, 0.005, 1%, 2 W, 2512", Manufacturer="Stackpole Electronics Inc", Power_W=2W, Supplier Part Number 1=CSNL2512FT5L00CT-ND, TempCo="50 ppm/C", Tolerance_%=1%, Value_Code=5L000, ValueDisplayed=0.005
R11: library part CMP-0015757-2, "RES, 0.004, 1%, 2 W, 2512", Manufacturer="Stackpole Electronics Inc", Power_W=2W, Supplier Part Number 1=CSNL2512FT4L00CT-ND, TempCo="50 ppm/C", Tolerance_%=1%, Value_Code=4L000, ValueDisplayed=0.004
R12: library part CMP-0022008-4, "RES, 110 k, 1%, 0.1 W, AEC-Q200 Grade 0, 0603", Manufacturer=Vishay-Dale, Power_W=100mW, Supplier Part Number 1=541-110KHCT-ND, TempCo="100 ppm/C", Tolerance_%=1%, Value2=0.1W, Value_Code=110k
R14 R15: library part CMP-0016583-3, "RES, 10.0, 1%, 0.25 W, AEC-Q200 Grade 0, 1206", Manufacturer=Vishay-Dale, Power_W=250mW, Supplier Part Number 1=541-10.0FCT-ND, TempCo="100 ppm/C", Tolerance_%=1%, Value2=0.25W, Value_Code=10R0, ValueDisplayed=10.0
R16 R19: library part CMP-0022201-5, "RES, 200, 1%, 0.1 W, AEC-Q200 Grade 0, 0603", Manufacturer=Vishay-Dale, Power_W=100mW, Supplier Part Number 1=541-200HCT-ND, TempCo="100 ppm/C", Tolerance_%=1%, Value2=0.1W, Value_Code=200R, ValueDisplayed=200
R17: library part CMP-0025697-1, "RES, 0, 5%, 0.1 W, 0603", Manufacturer=Vishay-Dale, Power_W=100mW, Supplier Part Number 1=541-0.0GCT-ND, TempCo="200 ppm/C", Tolerance_%=5%, Value2=0.1W, Value_Code=0000, ValueDisplayed=DNP
R20: library part CMP-0022268-4, "RES, 2.00 k, 1%, 0.1 W, AEC-Q200 Grade 0, 0603", Manufacturer=Vishay-Dale, Power_W=100mW, Supplier Part Number 1=541-2.00KHCT-ND, TempCo="100 ppm/C", Tolerance_%=1%, Value2=0.1W, Value_Code=2k00, ValueDisplayed=2.00k
R22 R23: library part CMP-0025698-4, "RES, 100 k, 5%, 0.1 W, AEC-Q200 Grade 0, 0603", Manufacturer=Vishay-Dale, Power_W=100mW, Supplier Part Number 1=541-100KGCT-ND, TempCo="200 ppm/C", Tolerance_%=5%, Value2=0.1W, Value_Code=100k
R25: library part CMP-0026605-2, "RES, 90.9 k, 1%, 0.063 W, AEC-Q200 Grade 0, 0402", Manufacturer=Vishay-Dale, Power_W=63mW, Supplier Part Number 1=541-90.9KLCT-ND, TempCo="100 ppm/C", Tolerance_%=1%, Value2=0.063W, Value_Code=90k9, ValueDisplayed=90.9k
R27: library part CMP-0025958-3, "RES, 10.0 k, 1%, 0.063 W, AEC-Q200 Grade 0, 0402", Manufacturer=Vishay-Dale, Power_W=63mW, Supplier Part Number 1=541-10.0KLCT-ND, TempCo="100 ppm/C", Tolerance_%=1%, Value2=0.063W, Value_Code=10k0, ValueDisplayed=10.0k
S1: library part CMP-0002118-3, "Switch, Toggle, SPDT 1Pos, TH", CurrentRating_mA=400A, Manufacturer="NKK Switches", Supplier Part Number 1=360-1769-ND
T1 T2: library part CMP-0055442-1, "Terminal 50A Lug", Manufacturer=Panduit, Supplier Part Number 1=CB35-36-CY-ND, Voltage_V=600V
TP1 TP2 TP7 TP8: library part CMP-0055147-1, "Test Point, Multipurpose, Red, TH", Color=Red, Manufacturer=Keystone, Supplier Part Number 1=36-5010-ND
TP3 TP4 TP6 TP9: library part CMP-0055148-1, "Test Point, Multipurpose, Black, TH", Color=Black, Manufacturer=Keystone, Supplier Part Number 1=36-5011-ND
TP5: library part CMP-0055151-1, "Test Point, Multipurpose, Yellow, TH", Color=Yellow, Manufacturer=Keystone, Supplier Part Number 1=36-5014-ND
U1: library part CMP-0081539-1, "Automotive Grade 2.2-MHz Wide Input Non-synchronous Boost Controller, DSS0012C (WSON-12)", Alternate Manufacturer="Texas Instruments", Alternate PartNumber=LM5155QDSSTQ1
U2: library part CMP-0067186-2, "Automotive Catalog Adjustable, 600-mA Switch, 90% Efficient PWM Boost Converter, DDC0006A (SOT-23-T-6)", Alternate Manufacturer="Texas Instruments"
U3: library part CMP-0033164-1, "Automotive Catalog Adjustable Precision Shunt Regulator, 34 ppm / degC, 100 mA, -40 to 125 degC, 3-pin SOT-23 (DBZ), Green (RoHS & no Sb/Br)", Manufacturer="Texas Instruments", Rating=Automotive, Temp Coeff(Typ)(ppm/ degree C)=34

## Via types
v1: diameter 0.6, hole 0.3, Top Layer to Bottom Layer, 191 vias
v2: diameter 0.813, hole 0.406, Top Layer to Bottom Layer, 56 vias
v3: diameter 5, hole 3, Top Layer to Bottom Layer, 4 vias
v4: diameter 0.5, hole 0.2, Top Layer to Bottom Layer, 3 vias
